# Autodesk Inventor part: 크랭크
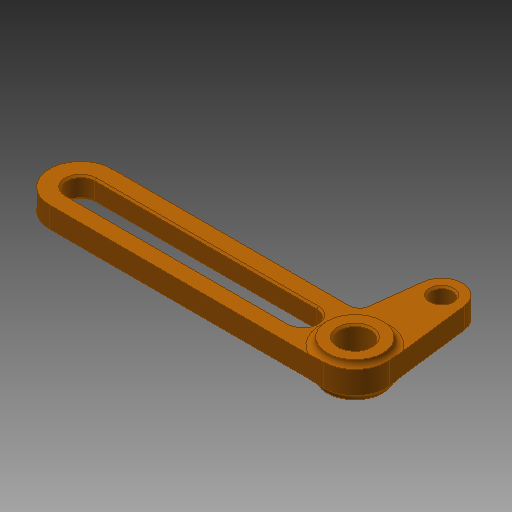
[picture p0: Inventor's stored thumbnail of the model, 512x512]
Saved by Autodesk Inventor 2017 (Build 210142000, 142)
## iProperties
Created: 2019-09
Part Number: 크랭크
Material: 알루미늄 6061
Document SubType Name: Modeling
Designer: mduedu
Density: 1 g/cm^3
Appearance: 주황색
Author: mduedu
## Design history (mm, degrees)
sketch "스케치1"
  geometry: L1 (0, 0)-(79, 0); L2 (0, 9)-(79, 9); L3 (10.637, -9)-(79, -9); L4 (0, 0)-(0, -25); L5 (-8.935, -1.08)-(-5.957, -25.72); L6 (7.659, -11.64)-(5.957, -25.72); L7 (79, -4)-(15, -4); L8 (15, 4)-(79, 4); C1 r 3 at (0, -25); A1 r 9 centre (0, 0) between (0, 9) and (-8.935, -1.08); A2 r 9 centre (79, 0) between (79, -9) and (79, 9); A3 r 6 centre (0, -25) between (-5.957, -25.72) and (5.957, -25.72); A4 r 3 centre (10.637, -12) between (10.637, -9) and (7.659, -11.64); A5 r 4 centre (79, 0) between (79, -4) and (79, 4); A6 r 4 centre (15, 0) between (15, -4) and (15, 4); 1 further point
  constraints: 16 end point, 13 point on circle, 12 tangent, 7 centre point, 5 coincident, 3 horizontal, 2 point on line, 1 equal radius, 1 perpendicular, 1 other
  dimensions: "d0" = 79 distance of L1.start L1.end; "d2" = 25 distance of L1.start L4.end; "d3" = 3 radius of A4; "d4" = 9 radius of A1; "d5" = 6 radius of A3; "d6" = 8 diameter of A5; "d7" = 64 distance of A6.centre L1.end; "d8" = 6 diameter of C1
extrude "돌출1" new body sketch "스케치1" stored distance "d9" = 6; taper "d10" = 0 deg
sketch "스케치2"
  geometry: C1 r 8 at (0, 0); 1 further point
  constraints: 1 centre point, 1 coincident
  dimensions: "d11" = 16 diameter of C1
extrude "돌출2" join sketch "스케치2" stored distance "d12" = 10; taper "d13" = 0 deg
sketch "스케치3"
  geometry: C1 r 4.5 at (0, 0); 1 further point
  constraints: 1 centre point, 1 coincident
  dimensions: "d14" = 9 diameter of C1
extrude "돌출3" cut sketch "스케치3" stored distance "d15" = 10; taper "d16" = 0 deg
fillet "모깎기1" dims "d17" = 2
chamfer "모따기1" distance "d18" = 0.5; stored, may be unused: second distance "d19" = 2, angle "d20" = 45 deg
node "솔리드1"
